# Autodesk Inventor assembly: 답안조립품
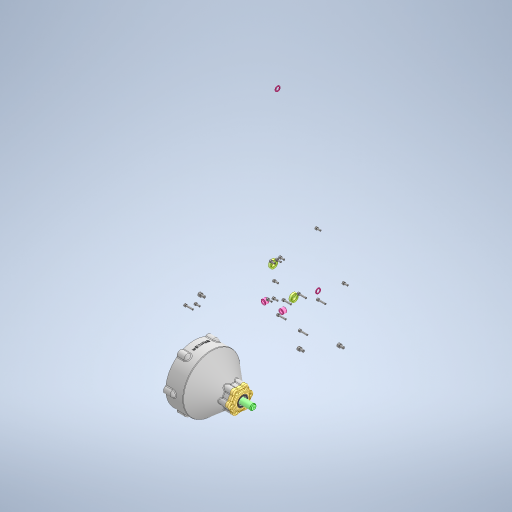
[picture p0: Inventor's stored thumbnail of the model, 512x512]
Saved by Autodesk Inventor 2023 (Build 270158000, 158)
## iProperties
Created: 2026-05
Part Number: 답안조립품
Document SubType Name: Assembly
Designer: home
Author: home
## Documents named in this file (19)
- C:\Users\home\Desktop\760503V1005\답안조립품.iam
- C:\Users\home\Desktop\760503V1005\본체.ipt
- C:\Users\home\Desktop\760403V1014\6각 구멍붙이 볼트 M4x10.ipt
- C:\Users\home\Desktop\760403V1014\6각 구멍붙이 볼트 M4x20.ipt
- C:\Users\home\Desktop\760403V1014\6각 구멍붙이 볼트 M6x10.ipt
- C:\Users\home\Desktop\760403V1014\깊은 홈 볼 베어링 6010.ipt
- C:\Users\home\Desktop\760403V1014\깊은 홈 볼 베어링 6203.ipt
- C:\Users\home\Desktop\760403V1014\깊은 홈 볼 베어링 6900.ipt
- C:\Users\home\Desktop\760403V1014\링 기어.ipt
- C:\Users\home\Desktop\760403V1014\선 기어 축.ipt
- C:\Users\home\Desktop\760403V1014\엔드 캡.ipt
- C:\Users\home\Desktop\760403V1014\오일 실 17 32 8.ipt
- C:\Users\home\Desktop\760403V1014\유성 기어.ipt
- C:\Users\home\Desktop\760403V1014\유성 축.ipt
- C:\Users\home\Desktop\760403V1014\유성 캐리어 커버.ipt
- C:\Users\home\Desktop\760403V1014\유성 캐리어.ipt
- C:\Users\home\Desktop\760403V1014\축용 C형 멈춤링 17.ipt
- C:\Users\home\Desktop\760403V1014\칼라.ipt
- C:\Users\home\Desktop\760403V1014\커버.ipt
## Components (18 placed, 3 different names)
1. 6각 구멍붙이 볼트 M4x10:1
2. 6각 구멍붙이 볼트 M4x10:2
3. 6각 구멍붙이 볼트 M4x10:3
4. 6각 구멍붙이 볼트 M4x10:4
5. 6각 구멍붙이 볼트 M4x10:5
6. 6각 구멍붙이 볼트 M4x10:6
7. 6각 구멍붙이 볼트 M4x10:7
8. 6각 구멍붙이 볼트 M4x10:8
9. 6각 구멍붙이 볼트 M4x10:9
10. 6각 구멍붙이 볼트 M6x10:1
11. 6각 구멍붙이 볼트 M6x10:2
12. 6각 구멍붙이 볼트 M6x10:3
13. 6각 구멍붙이 볼트 M4x20:1
14. 6각 구멍붙이 볼트 M4x20:2
15. 6각 구멍붙이 볼트 M4x20:3
16. 6각 구멍붙이 볼트 M4x20:4
17. 6각 구멍붙이 볼트 M4x20:5
18. 6각 구멍붙이 볼트 M4x20:6
